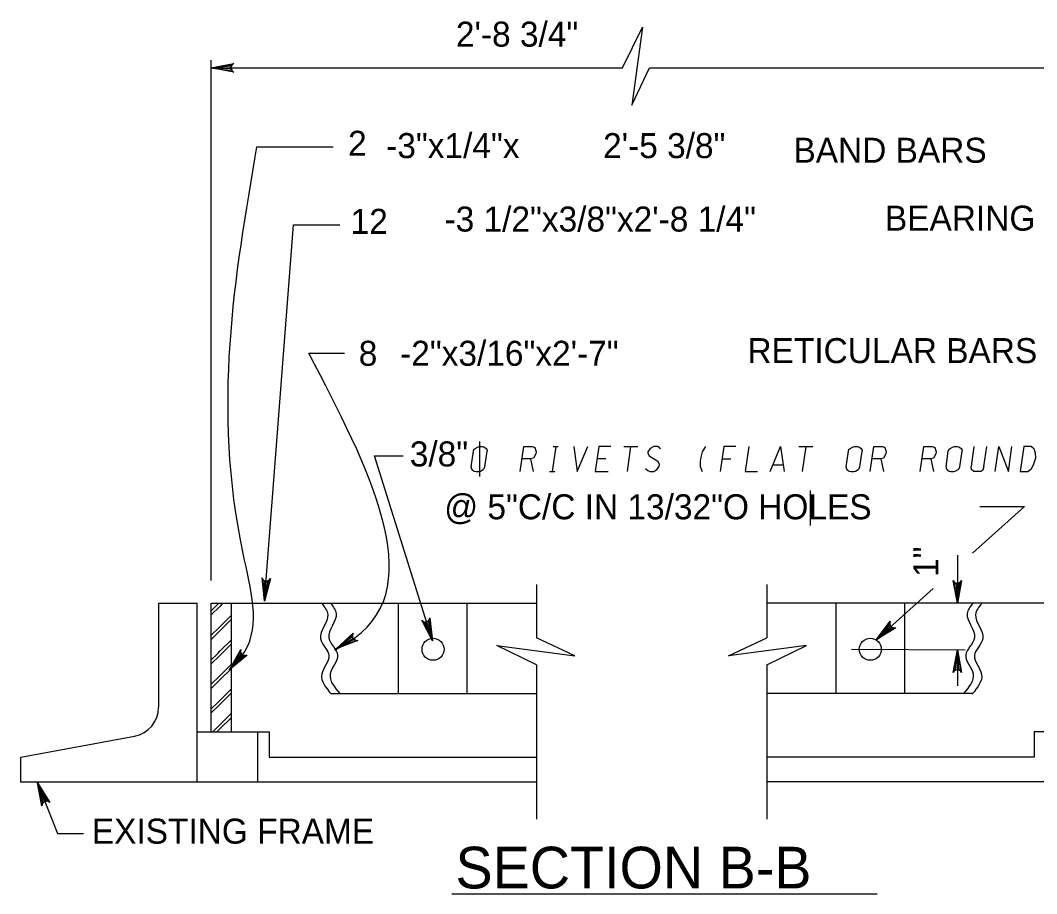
# Model space of a CAD drawing. Extents: x -0.3 to 6.9, y -6.5 to 3.5.
# Drawn here: x -0.056 to 2.383, y -4.865 to -2.771 of the extents above; entities that cross this region are included whole.
import ezdxf

# ---------------------------------------------------------------- set-up
doc = ezdxf.new("R2010")
doc.units = 0
for name, color, linetype in [('DETL-DIMS', 7, 'Continuous'), ('DETL-LINE', 7, 'Continuous'), ('DETL-NOTE', 7, 'Continuous'), ('DETL-PATT', 7, 'Continuous'), ('DETL-TITL', 7, 'Continuous')]:
    doc.layers.add(name, color=color, linetype=linetype)

msp = doc.modelspace()

# ---------------------------------------------------------------- linework, layer by layer
at = {"layer": 'DETL-DIMS'}
for p, q in [((0.4015, -2.8661), (0.4015, -4.1145)), ((0.4015, -2.8843), (1.3895, -2.8843)), ((1.4542, -2.8843), (2.517, -2.8843)), ((0.5119, -3.0739), (0.6946, -3.0739)), ((0.5302, -4.1636), (0.5999, -3.261)), ((0.5999, -3.261), (0.7109, -3.261)), ((0.6365, -3.5692), (0.7224, -3.5692)), ((0.9336, -4.259), (0.7942, -3.815)), ((0.7942, -3.815), (0.8632, -3.815)), ((2.2293, -4.0488), (2.3544, -3.9366)), ((2.2471, -3.9366), (2.3544, -3.9366)), ((2.1929, -4.0535), (2.1929, -4.169)), ((1.9977, -4.2564), (2.135, -4.1333)), ((1.939, -4.279), (2.2119, -4.2807)), ((2.1929, -4.2804), (2.1929, -4.3667)), ((-0.0148, -4.5997), (0.0332, -4.7212)), ((0.0332, -4.7212), (0.0955, -4.7212))]:
    msp.add_line(p, q, dxfattribs=at)
for points in [[(1.3895, -2.8843), (1.437, -2.7874), (1.4116, -2.974), (1.4542, -2.8843)], [(0.4015, -2.8843), (0.4563, -2.8741), (0.4521, -2.877), (0.4499, -2.8807), (0.4493, -2.8843), (0.4499, -2.888), (0.4521, -2.8917), (0.4563, -2.8946), (0.4015, -2.8843), (0.4521, -2.8917), (0.4499, -2.888), (0.4015, -2.8843), (0.4493, -2.8843), (0.4499, -2.8807), (0.4015, -2.8843), (0.4521, -2.877)], [(0.4015, -2.8843), (0.4563, -2.8741), (0.4521, -2.877), (0.4499, -2.8807), (0.4493, -2.8843), (0.4499, -2.888), (0.4521, -2.8917), (0.4563, -2.8946), (0.4015, -2.8843), (0.4521, -2.8917), (0.4499, -2.888), (0.4015, -2.8843), (0.4493, -2.8843), (0.4499, -2.8807), (0.4015, -2.8843), (0.4521, -2.877)], [(0.5302, -4.1636), (0.5242, -4.1081), (0.5268, -4.1126), (0.5303, -4.115), (0.5339, -4.1159), (0.5376, -4.1156), (0.5414, -4.1137), (0.5447, -4.1097), (0.5302, -4.1636), (0.5414, -4.1137), (0.5376, -4.1156), (0.5302, -4.1636), (0.5339, -4.1159), (0.5303, -4.115), (0.5302, -4.1636), (0.5268, -4.1126)], [(2.1929, -4.169), (2.1826, -4.1142), (2.1856, -4.1184), (2.1892, -4.1206), (2.1929, -4.1212), (2.1966, -4.1206), (2.2003, -4.1184), (2.2032, -4.1142), (2.1929, -4.169), (2.2003, -4.1184), (2.1966, -4.1206), (2.1929, -4.169), (2.1929, -4.1212), (2.1892, -4.1206), (2.1929, -4.169), (2.1856, -4.1184)], [(2.1929, -4.169), (2.1826, -4.1142), (2.1856, -4.1184), (2.1892, -4.1206), (2.1929, -4.1212), (2.1966, -4.1206), (2.2003, -4.1184), (2.2032, -4.1142), (2.1929, -4.169), (2.2003, -4.1184), (2.1966, -4.1206), (2.1929, -4.169), (2.1929, -4.1212), (2.1892, -4.1206), (2.1929, -4.169), (2.1856, -4.1184)], [(0.9336, -4.259), (0.9073, -4.2098), (0.9114, -4.2129), (0.9156, -4.2139), (0.9193, -4.2134), (0.9226, -4.2117), (0.9254, -4.2085), (0.927, -4.2036), (0.9336, -4.259), (0.9254, -4.2085), (0.9226, -4.2117), (0.9336, -4.259), (0.9193, -4.2134), (0.9156, -4.2139), (0.9336, -4.259), (0.9114, -4.2129)], [(1.9977, -4.2564), (2.0317, -4.2122), (2.0305, -4.2172), (2.0313, -4.2213), (2.0333, -4.2245), (2.0362, -4.2268), (2.0403, -4.2281), (2.0454, -4.2275), (1.9977, -4.2564), (2.0403, -4.2281), (2.0362, -4.2268), (1.9977, -4.2564), (2.0333, -4.2245), (2.0313, -4.2213), (1.9977, -4.2564), (2.0305, -4.2172)], [(0.7021, -4.2785), (0.7432, -4.2408), (0.7412, -4.2455), (0.7413, -4.2498), (0.7427, -4.2532), (0.7452, -4.256), (0.749, -4.258), (0.7541, -4.2582), (0.7021, -4.2785), (0.749, -4.258), (0.7452, -4.256), (0.7021, -4.2785), (0.7427, -4.2532), (0.7413, -4.2498), (0.7021, -4.2785), (0.7412, -4.2455)], [(0.4459, -4.3287), (0.4731, -4.28), (0.4726, -4.2851), (0.474, -4.2891), (0.4764, -4.292), (0.4797, -4.2939), (0.4839, -4.2945), (0.4888, -4.2932), (0.4459, -4.3287), (0.4839, -4.2945), (0.4797, -4.2939), (0.4459, -4.3287), (0.4764, -4.292), (0.474, -4.2891), (0.4459, -4.3287), (0.4726, -4.2851)], [(2.1929, -4.2804), (2.2032, -4.3353), (2.2003, -4.331), (2.1966, -4.3289), (2.1929, -4.3282), (2.1892, -4.3289), (2.1856, -4.331), (2.1826, -4.3353), (2.1929, -4.2804), (2.1856, -4.331), (2.1892, -4.3289), (2.1929, -4.2804), (2.1929, -4.3282), (2.1966, -4.3289), (2.1929, -4.2804), (2.2003, -4.331)], [(-0.0148, -4.5997), (0.0149, -4.647), (0.0106, -4.6441), (0.0064, -4.6434), (0.0027, -4.6442), (-0.0004, -4.6461), (-0.0031, -4.6495), (-0.0042, -4.6545), (-0.0148, -4.5997), (-0.0031, -4.6495), (-0.0004, -4.6461), (-0.0148, -4.5997), (0.0027, -4.6442), (0.0064, -4.6434), (-0.0148, -4.5997), (0.0106, -4.6441)]]:
    msp.add_lwpolyline(points, dxfattribs=at)
for points in [[(0.4459, -4.3287), (0.4825, -4.2847), (0.4789, -4.0499), (0.5119, -3.0739)], [(0.6989, -4.281), (0.7466, -4.2517), (0.6365, -3.5692)]]:
    msp.add_spline(points, degree=3, dxfattribs=at)
at = {"layer": 'DETL-LINE'}
for p, q in [((1.1829, -4.1239), (1.1829, -4.2516)), ((1.7356, -4.1239), (1.7356, -4.2516)), ((0.2757, -4.169), (0.2757, -4.4183)), ((0.2757, -4.169), (0.3675, -4.169)), ((0.3675, -4.169), (0.3675, -4.597)), ((0.4015, -4.169), (0.4015, -4.477)), ((0.4015, -4.169), (1.1829, -4.169)), ((0.4497, -4.169), (0.4497, -4.477)), ((0.8514, -4.3852), (0.8514, -4.169)), ((1.0166, -4.3852), (1.0166, -4.169)), ((2.517, -4.169), (1.7356, -4.169)), ((1.9019, -4.3852), (1.9019, -4.169)), ((2.0671, -4.3852), (2.0671, -4.169)), ((1.1829, -4.3163), (1.1829, -4.6865)), ((1.7356, -4.3163), (1.7356, -4.6865)), ((0.6896, -4.3852), (1.1829, -4.3852)), ((2.2289, -4.3852), (1.7356, -4.3852)), ((-0.0551, -4.5381), (0.218, -4.4877)), ((0.3675, -4.477), (0.5416, -4.477)), ((0.5134, -4.477), (0.5134, -4.597)), ((0.5416, -4.477), (0.5416, -4.5383)), ((2.551, -4.477), (2.3769, -4.477)), ((2.3769, -4.477), (2.3769, -4.5383)), ((-0.056, -4.5383), (-0.056, -4.597)), ((0.5416, -4.5383), (1.1829, -4.5383)), ((2.3769, -4.5383), (1.7356, -4.5383)), ((-0.056, -4.597), (1.1829, -4.597)), ((2.9745, -4.597), (1.7356, -4.597))]:
    msp.add_line(p, q, dxfattribs=at)
for points in [[(1.1829, -4.3163), (1.088, -4.2699), (1.2746, -4.2952), (1.1829, -4.2516)], [(1.7356, -4.3163), (1.8305, -4.2699), (1.6439, -4.2952), (1.7356, -4.2516)]]:
    msp.add_lwpolyline(points, dxfattribs=at)
for centre in [(0.9345, -4.2793), (1.984, -4.2793)]:
    msp.add_circle(centre, 0.0264, dxfattribs=at)
msp.add_arc((0.2052, -4.4183), 0.0706, 280.4675, 0, dxfattribs=at)
for points in [[(0.6673, -4.1696), (0.6818, -4.1957), (0.6644, -4.2537), (0.6847, -4.2943), (0.6673, -4.3392), (0.6905, -4.3871)], [(0.6885, -4.169), (0.7021, -4.1935), (0.6845, -4.2519), (0.7052, -4.2933), (0.6878, -4.3384), (0.7108, -4.3856)], [(2.23, -4.169), (2.2164, -4.1935), (2.2339, -4.2519), (2.2132, -4.2933), (2.2307, -4.3384), (2.2077, -4.3856)], [(2.2512, -4.1696), (2.2367, -4.1957), (2.2541, -4.2537), (2.2338, -4.2943), (2.2512, -4.3392), (2.228, -4.3871)]]:
    msp.add_spline(points, degree=3, dxfattribs=at)
at = {"layer": 'DETL-NOTE'}
for p, q in [((1.0461, -3.781), (1.0461, -3.8651)), ((1.0461, -3.781), (1.0461, -3.8651)), ((1.0461, -3.781), (1.0461, -3.8651)), ((1.0461, -3.781), (1.0461, -3.8651)), ((1.8398, -3.8981), (1.8398, -3.9821))]:
    msp.add_line(p, q, dxfattribs=at)
for points in [[(1.026, -3.8417), (1.0313, -3.8044)], [(1.0313, -3.8044), (1.0326, -3.8002), (1.0358, -3.7973), (1.0413, -3.7945), (1.0462, -3.7931), (1.0529, -3.7931), (1.0563, -3.794), (1.0621, -3.7978), (1.0637, -3.8002), (1.0643, -3.8044)], [(1.0591, -3.8417), (1.0643, -3.8044)], [(1.1437, -3.8531), (1.1521, -3.7931), (1.173, -3.7931)], [(1.173, -3.7931), (1.179, -3.7954), (1.1819, -3.8054), (1.1812, -3.8106), (1.1754, -3.8205), (1.1688, -3.8228)], [(1.2289, -3.7931), (1.2205, -3.8531)], [(1.2226, -3.7931), (1.2352, -3.7931)], [(1.2722, -3.7931), (1.2803, -3.8531), (1.3057, -3.7931)], [(1.3616, -3.7931), (1.3325, -3.7931), (1.324, -3.8531), (1.3551, -3.8531)], [(1.3923, -3.7931), (1.4258, -3.7931)], [(1.4088, -3.7931), (1.4004, -3.8531)], [(1.477, -3.7954), (1.473, -3.7931), (1.4647, -3.7931), (1.4554, -3.7978), (1.4504, -3.8054), (1.4501, -3.8077), (1.453, -3.8153)], [(1.477, -3.7954), (1.4806, -3.7978)], [(1.5887, -3.7931), (1.5807, -3.8054), (1.577, -3.8181), (1.5756, -3.828), (1.5757, -3.8408), (1.5803, -3.8531)], [(1.6616, -3.7931), (1.6325, -3.7931), (1.624, -3.8531)], [(1.6923, -3.7931), (1.6839, -3.8531), (1.713, -3.8531)], [(1.7437, -3.8531), (1.7687, -3.7931), (1.7772, -3.8531)], [(1.8124, -3.7931), (1.8458, -3.7931)], [(1.8289, -3.7931), (1.8205, -3.8531)], [(1.926, -3.8417), (1.9313, -3.8044)], [(1.9313, -3.8044), (1.9326, -3.8002), (1.9358, -3.7973), (1.9413, -3.7945), (1.9462, -3.7931), (1.9529, -3.7931), (1.9563, -3.794), (1.9621, -3.7978), (1.9637, -3.8002), (1.9643, -3.8044)], [(1.9591, -3.8417), (1.9643, -3.8044)], [(1.9839, -3.8531), (1.9923, -3.7931), (2.0132, -3.7931)], [(2.0132, -3.7931), (2.0191, -3.7954), (2.0221, -3.8054), (2.0213, -3.8106), (2.0156, -3.8205), (2.009, -3.8228)], [(2.1039, -3.8531), (2.1124, -3.7931), (2.1332, -3.7931)], [(2.1332, -3.7931), (2.1392, -3.7954), (2.1421, -3.8054), (2.1414, -3.8106), (2.1357, -3.8205), (2.1291, -3.8228)], [(2.1658, -3.8417), (2.171, -3.8044)], [(2.171, -3.8044), (2.1724, -3.8002), (2.1756, -3.7973), (2.1811, -3.7945), (2.186, -3.7931), (2.1927, -3.7931), (2.1961, -3.794), (2.2019, -3.7978), (2.2035, -3.8002), (2.2041, -3.8044)], [(2.1988, -3.8417), (2.2041, -3.8044)], [(2.2325, -3.7931), (2.2257, -3.8408)], [(2.2568, -3.8408), (2.2636, -3.7931)], [(2.2839, -3.8531), (2.2923, -3.7931), (2.3154, -3.8531), (2.3238, -3.7931)], [(2.371, -3.7931), (2.3521, -3.7931), (2.3437, -3.8531), (2.3626, -3.8531)], [(2.371, -3.7931), (2.3767, -3.7978), (2.3796, -3.8077), (2.3801, -3.821), (2.375, -3.8375), (2.3696, -3.8484), (2.3626, -3.8531)], [(1.1688, -3.8228), (1.148, -3.8228)], [(1.1688, -3.8228), (1.1752, -3.8531)], [(1.3491, -3.8228), (1.3283, -3.8228)], [(1.4503, -3.8507), (1.4552, -3.8526), (1.4646, -3.8526), (1.4715, -3.8484), (1.4769, -3.8408), (1.4777, -3.8356), (1.4744, -3.828)], [(1.453, -3.8153), (1.4744, -3.828)], [(1.6283, -3.8228), (1.6491, -3.8228)], [(2.009, -3.8228), (1.9881, -3.8228)], [(2.009, -3.8228), (2.0154, -3.8531)], [(2.1291, -3.8228), (2.1082, -3.8228)], [(2.1291, -3.8228), (2.1354, -3.8531)], [(1.026, -3.8417), (1.0262, -3.846), (1.0286, -3.8488), (1.0333, -3.8517), (1.0378, -3.8531), (1.0445, -3.8531), (1.0482, -3.8521), (1.055, -3.8484), (1.0573, -3.846), (1.0591, -3.8417)], [(1.2142, -3.8531), (1.2268, -3.8531)], [(1.4448, -3.8455), (1.4503, -3.8507)], [(1.775, -3.838), (1.7502, -3.838)], [(1.926, -3.8417), (1.9262, -3.846), (1.9286, -3.8488), (1.9333, -3.8517), (1.9378, -3.8531), (1.9445, -3.8531), (1.9482, -3.8521), (1.955, -3.8484), (1.9573, -3.846), (1.9591, -3.8417)], [(2.1658, -3.8417), (2.166, -3.846), (2.1683, -3.8488), (2.173, -3.8517), (2.1776, -3.8531), (2.1843, -3.8531), (2.1879, -3.8521), (2.1948, -3.8484), (2.1971, -3.846), (2.1988, -3.8417)], [(2.2568, -3.8408), (2.2537, -3.8493), (2.2492, -3.8531), (2.2323, -3.8531), (2.2267, -3.8484), (2.2257, -3.8408)]]:
    msp.add_lwpolyline(points, dxfattribs=at)
at = {"layer": 'DETL-PATT'}
for p, q in [((0.4177, -4.1714), (0.4201, -4.169)), ((0.4277, -4.1714), (0.4301, -4.169)), ((0.4015, -4.1877), (0.4177, -4.1714)), ((0.4015, -4.1975), (0.4226, -4.1763)), ((0.4277, -4.1714), (0.4226, -4.1765)), ((0.4228, -4.2253), (0.4497, -4.1984)), ((0.4497, -4.2082), (0.4228, -4.2351)), ((0.4015, -4.2465), (0.4226, -4.2253)), ((0.4015, -4.2563), (0.4226, -4.2351)), ((0.4228, -4.2841), (0.4497, -4.2573)), ((0.4277, -4.2891), (0.4497, -4.2671)), ((0.4015, -4.3053), (0.4177, -4.2891)), ((0.4177, -4.2891), (0.4226, -4.2841)), ((0.4277, -4.2891), (0.4226, -4.2942)), ((0.4015, -4.3151), (0.4226, -4.294)), ((0.4228, -4.343), (0.4497, -4.3161)), ((0.4497, -4.3259), (0.4228, -4.3528)), ((0.4015, -4.3641), (0.4226, -4.343)), ((0.4015, -4.3739), (0.4226, -4.3528)), ((0.4228, -4.4018), (0.4497, -4.3749)), ((0.4277, -4.4067), (0.4497, -4.3847)), ((0.4015, -4.423), (0.4177, -4.4067)), ((0.4015, -4.4328), (0.4226, -4.4116)), ((0.4177, -4.4067), (0.4226, -4.4018)), ((0.4277, -4.4067), (0.4226, -4.4118)), ((0.4228, -4.4606), (0.4497, -4.4337)), ((0.4062, -4.477), (0.4226, -4.4606)), ((0.4497, -4.4435), (0.4228, -4.4704)), ((0.416, -4.477), (0.4226, -4.4704))]:
    msp.add_line(p, q, dxfattribs=at)
at = {"layer": 'DETL-TITL'}
msp.add_line((0.9797, -4.8655), (2.0001, -4.8655), dxfattribs=at)

# ---------------------------------------------------------------- texts
at = {"layer": 'DETL-NOTE'}
for s, p in [('2\'-8 3/4"', (0.9895, -2.8338)), ('2', (0.7307, -3.0956)), ('-3"x1/4"x', (0.822, -3.1011)), ('2\'-5 3/8"', (1.3427, -3.1012)), ('BAND BARS', (1.7996, -3.1122)), ('-3 1/2"x3/8"x2\'-8 1/4"', (0.9621, -3.2773)), ('BEARING BARS', (2.0191, -3.2751)), ('12', (0.7367, -3.2828)), ('-2"x3/16"x2\'-7"', (0.8555, -3.5993)), ('RETICULAR BARS', (1.6892, -3.5929)), ('8', (0.7562, -3.5993)), ('3/8"', (0.8787, -3.8407)), ('@ 5"C/C IN 13/32"O HOLES', (0.9613, -3.9675)), ('EXISTING FRAME', (0.1156, -4.7455))]:
    msp.add_text(s, height=0.06, dxfattribs=at).set_placement(p)
msp.add_text('1"', height=0.06, rotation=90, dxfattribs=at).set_placement((2.147, -4.1058))
at = {"layer": 'DETL-TITL'}
msp.add_text('SECTION B-B', height=0.1, dxfattribs=at).set_placement((0.9884, -4.8529))

doc.saveas('drawing.dxf')
